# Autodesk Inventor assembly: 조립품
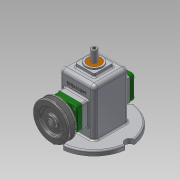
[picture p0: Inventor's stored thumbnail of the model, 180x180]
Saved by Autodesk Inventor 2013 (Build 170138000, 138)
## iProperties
Created: 2018-07
Part Number: 조립품
Document SubType Name: Assembly
Designer: Administrator
Author: Administrator
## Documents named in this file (16)
- C:\Users\Administrator\Desktop\480707V1006\조립품.iam
- C:\Users\Administrator\Desktop\480707V1006\V벨트풀리.ipt
- C:\Users\Administrator\Desktop\480707V1006\고정핀 1.2x8.ipt
- C:\Users\Administrator\Desktop\480707V1006\뒤커버.ipt
- C:\Users\Administrator\Desktop\480707V1006\링크.ipt
- C:\Users\Administrator\Desktop\480707V1006\멈춤나사 M3x8.ipt
- C:\Users\Administrator\Desktop\480707V1006\베어링 12x32x10.ipt
- C:\Users\Administrator\Desktop\480707V1006\본체.ipt
- C:\Users\Administrator\Desktop\480707V1006\볼트 M4.ipt
- C:\Users\Administrator\Desktop\480707V1006\부시.ipt
- C:\Users\Administrator\Desktop\480707V1006\슬라이드.ipt
- C:\Users\Administrator\Desktop\480707V1006\앞커버.ipt
- C:\Users\Administrator\Desktop\480707V1006\오일 실 12 25 7.ipt
- C:\Users\Administrator\Desktop\480707V1006\키 4x4x10.ipt
- C:\Users\Administrator\Desktop\480707V1006\편심축.ipt
- C:\Users\Administrator\Desktop\480707V1006\핀 5x18.ipt
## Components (3 placed, 3 different names)
1. V벨트풀리:1 — 플러쉬:1
2. 고정핀 1.2x8:1
3. 핀 5x18:1
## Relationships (1: Flush 1)
- 플러쉬:1 [Flush]: V벨트풀리:1
